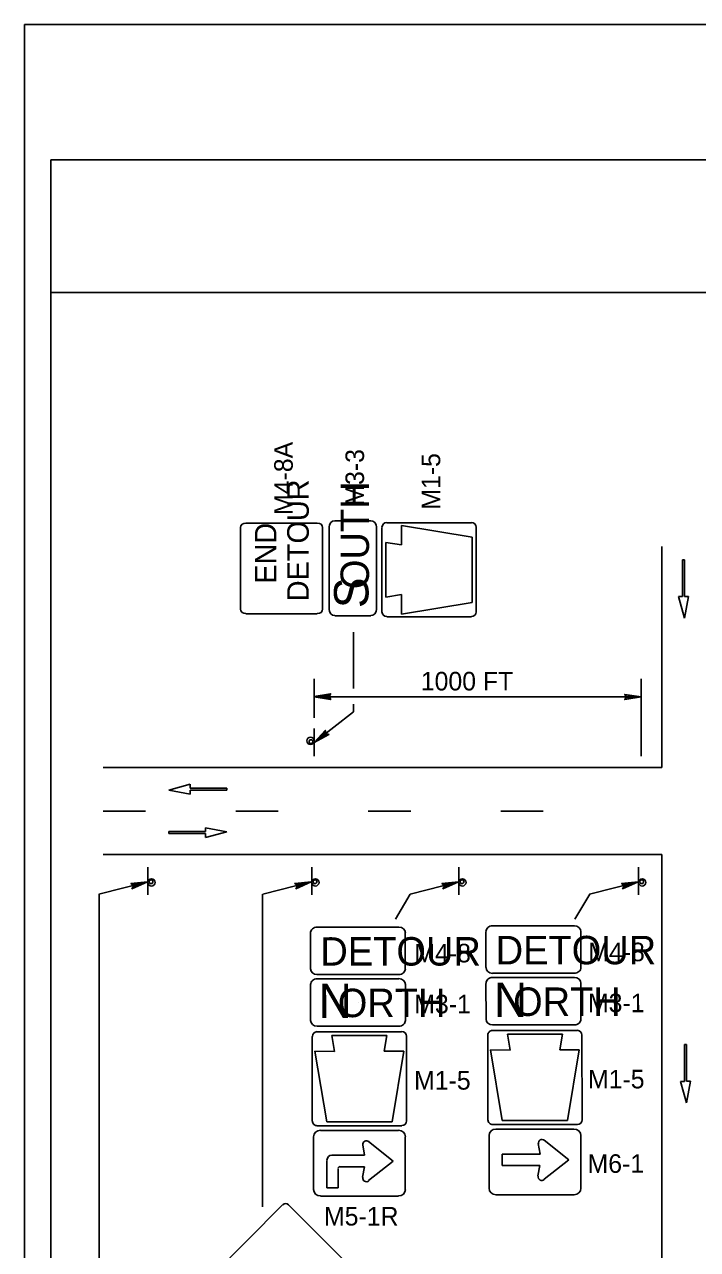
# Model space of a CAD drawing. Extents: x -14145 to -13521, y 30244 to 30661.
# Drawn here: x -13926.17 to -13918.56, y 30274.45 to 30288.31 of the extents above; entities that cross this region are included whole.
import ezdxf

# ---------------------------------------------------------------- set-up
doc = ezdxf.new("R2010")
doc.units = 0
for name, color, linetype in [('1', 7, 'Continuous'), ('10', 7, 'Continuous'), ('2', 7, 'Continuous'), ('61', 7, 'Continuous')]:
    doc.layers.add(name, color=color, linetype=linetype)

msp = doc.modelspace()

# ---------------------------------------------------------------- linework, layer by layer
at = {"layer": '1'}
for p, q in [((-13923.73, 30281.692), (-13923.73, 30282.619)), ((-13923.67, 30282.668), (-13922.863, 30282.668)), ((-13922.803, 30282.619), (-13922.803, 30281.692)), ((-13922.729, 30282.619), (-13922.729, 30281.692)), ((-13922.257, 30282.692), (-13922.663, 30282.692)), ((-13922.192, 30281.692), (-13922.192, 30282.619)), ((-13922.13, 30282.619), (-13922.13, 30281.661)), ((-13921.119, 30282.672), (-13922.077, 30282.672)), ((-13921.111, 30282.509), (-13921.909, 30282.642)), ((-13921.909, 30282.642), (-13921.909, 30282.421)), ((-13921.066, 30281.661), (-13921.066, 30282.619)), ((-13921.909, 30282.421), (-13922.087, 30282.45)), ((-13922.087, 30282.45), (-13922.087, 30282.14)), ((-13921.111, 30282.132), (-13921.111, 30282.509)), ((-13918.966, 30279.902), (-13918.966, 30282.402)), ((-13918.708, 30282.252), (-13918.73, 30282.252)), ((-13918.73, 30282.252), (-13918.73, 30281.836)), ((-13918.708, 30281.838), (-13918.708, 30282.252)), ((-13922.087, 30282.14), (-13922.087, 30281.829)), ((-13921.111, 30281.771), (-13921.111, 30282.148)), ((-13922.087, 30281.829), (-13921.909, 30281.859)), ((-13921.909, 30281.859), (-13921.909, 30281.637)), ((-13921.909, 30281.637), (-13921.111, 30281.771)), ((-13918.73, 30281.836), (-13918.776, 30281.836)), ((-13918.776, 30281.836), (-13918.709, 30281.594)), ((-13918.709, 30281.594), (-13918.663, 30281.838)), ((-13918.663, 30281.838), (-13918.708, 30281.838)), ((-13922.863, 30281.643), (-13923.67, 30281.643)), ((-13922.663, 30281.619), (-13922.257, 30281.619)), ((-13922.077, 30281.607), (-13921.119, 30281.607)), ((-13922.453, 30280.798), (-13922.453, 30281.436)), ((-13922.898, 30280.905), (-13922.898, 30280.465)), ((-13919.198, 30280.905), (-13919.198, 30280.031)), ((-13919.198, 30280.701), (-13922.898, 30280.701)), ((-13919.198, 30280.701), (-13921.048, 30280.701)), ((-13919.198, 30280.701), (-13921.048, 30280.701)), ((-13922.454, 30280.535), (-13922.899, 30280.187)), ((-13922.453, 30280.535), (-13922.453, 30280.619)), ((-13922.899, 30280.031), (-13922.899, 30280.343)), ((-13922.899, 30280.031), (-13922.899, 30280.343)), ((-13922.899, 30280.031), (-13922.899, 30280.343)), ((-13922.899, 30280.031), (-13922.899, 30280.343)), ((-13922.899, 30280.031), (-13922.899, 30280.343)), ((-13922.899, 30280.031), (-13922.899, 30280.343)), ((-13925.284, 30279.902), (-13918.966, 30279.902)), ((-13924.301, 30279.714), (-13924.542, 30279.647)), ((-13924.301, 30279.668), (-13924.301, 30279.714)), ((-13923.884, 30279.668), (-13924.301, 30279.668)), ((-13923.884, 30279.646), (-13923.884, 30279.668)), ((-13924.542, 30279.647), (-13924.298, 30279.601)), ((-13924.298, 30279.601), (-13924.298, 30279.646)), ((-13924.298, 30279.646), (-13923.884, 30279.646)), ((-13924.805, 30279.411), (-13925.285, 30279.411)), ((-13923.305, 30279.411), (-13923.785, 30279.411)), ((-13921.805, 30279.411), (-13922.285, 30279.411)), ((-13920.305, 30279.411), (-13920.785, 30279.411)), ((-13924.128, 30279.178), (-13924.542, 30279.178)), ((-13924.542, 30279.178), (-13924.542, 30279.156)), ((-13924.542, 30279.156), (-13924.126, 30279.156)), ((-13923.884, 30279.177), (-13924.128, 30279.223)), ((-13924.128, 30279.223), (-13924.128, 30279.178)), ((-13924.126, 30279.111), (-13923.884, 30279.177)), ((-13924.126, 30279.156), (-13924.126, 30279.111)), ((-13925.284, 30278.918), (-13918.966, 30278.918)), ((-13918.966, 30270.956), (-13918.966, 30278.918)), ((-13924.778, 30278.777), (-13924.778, 30278.465)), ((-13924.778, 30278.777), (-13924.778, 30278.465)), ((-13924.778, 30278.777), (-13924.778, 30278.465)), ((-13924.778, 30278.777), (-13924.778, 30278.465)), ((-13924.778, 30278.777), (-13924.778, 30278.465)), ((-13924.778, 30278.777), (-13924.778, 30278.465)), ((-13922.924, 30278.777), (-13922.924, 30278.465)), ((-13922.924, 30278.777), (-13922.924, 30278.465)), ((-13922.924, 30278.777), (-13922.924, 30278.465)), ((-13922.924, 30278.777), (-13922.924, 30278.465)), ((-13922.924, 30278.777), (-13922.924, 30278.465)), ((-13922.924, 30278.777), (-13922.924, 30278.465)), ((-13921.26, 30278.777), (-13921.26, 30278.465)), ((-13921.26, 30278.777), (-13921.26, 30278.465)), ((-13921.26, 30278.777), (-13921.26, 30278.465)), ((-13921.26, 30278.777), (-13921.26, 30278.465)), ((-13921.26, 30278.777), (-13921.26, 30278.465)), ((-13921.26, 30278.777), (-13921.26, 30278.465)), ((-13919.228, 30278.777), (-13919.228, 30278.465)), ((-13919.228, 30278.777), (-13919.228, 30278.465)), ((-13919.228, 30278.777), (-13919.228, 30278.465)), ((-13919.228, 30278.777), (-13919.228, 30278.465)), ((-13919.228, 30278.777), (-13919.228, 30278.465)), ((-13919.228, 30278.777), (-13919.228, 30278.465)), ((-13925.331, 30278.47), (-13924.784, 30278.61)), ((-13925.331, 30278.47), (-13924.784, 30278.61)), ((-13923.477, 30278.47), (-13922.93, 30278.61)), ((-13923.477, 30278.47), (-13922.93, 30278.61)), ((-13921.813, 30278.47), (-13921.266, 30278.61)), ((-13921.813, 30278.47), (-13921.266, 30278.61)), ((-13919.781, 30278.47), (-13919.234, 30278.61)), ((-13919.781, 30278.47), (-13919.234, 30278.61)), ((-13925.33, 30278.47), (-13925.33, 30273.816)), ((-13923.48, 30278.47), (-13923.48, 30274.934)), ((-13921.812, 30278.47), (-13921.979, 30278.188)), ((-13919.78, 30278.47), (-13919.947, 30278.188)), ((-13922.94, 30277.627), (-13922.94, 30278.032)), ((-13922.866, 30278.098), (-13921.94, 30278.098)), ((-13921.866, 30278.032), (-13921.866, 30277.627)), ((-13920.955, 30277.641), (-13920.955, 30278.046)), ((-13920.881, 30278.113), (-13919.955, 30278.113)), ((-13919.881, 30278.047), (-13919.881, 30277.642)), ((-13922.938, 30277.042), (-13922.939, 30277.448)), ((-13921.94, 30277.561), (-13922.866, 30277.561)), ((-13922.865, 30277.514), (-13921.938, 30277.514)), ((-13921.865, 30277.448), (-13921.865, 30277.042)), ((-13920.953, 30277.056), (-13920.954, 30277.462)), ((-13919.955, 30277.576), (-13920.881, 30277.576)), ((-13920.881, 30277.529), (-13919.954, 30277.529)), ((-13919.881, 30277.463), (-13919.88, 30277.057)), ((-13922.401, 30277.245), (-13922.401, 30277.245)), ((-13920.416, 30277.259), (-13920.416, 30277.259)), ((-13922.866, 30276.915), (-13921.908, 30276.915)), ((-13921.938, 30276.977), (-13922.865, 30276.977)), ((-13919.953, 30276.992), (-13920.88, 30276.992)), ((-13920.88, 30276.93), (-13919.922, 30276.93)), ((-13920.682, 30276.708), (-13920.711, 30276.887)), ((-13920.711, 30276.887), (-13920.401, 30276.887)), ((-13920.401, 30276.887), (-13920.09, 30276.887)), ((-13920.09, 30276.887), (-13920.12, 30276.709)), ((-13922.918, 30275.904), (-13922.918, 30276.862)), ((-13922.667, 30276.693), (-13922.696, 30276.872)), ((-13922.696, 30276.872), (-13922.386, 30276.872)), ((-13922.386, 30276.872), (-13922.075, 30276.872)), ((-13922.075, 30276.872), (-13922.105, 30276.694)), ((-13921.853, 30276.862), (-13921.852, 30275.904)), ((-13920.932, 30275.918), (-13920.934, 30276.876)), ((-13919.868, 30276.877), (-13919.867, 30275.919)), ((-13918.685, 30276.769), (-13918.707, 30276.769)), ((-13918.707, 30276.769), (-13918.707, 30276.353)), ((-13918.685, 30276.355), (-13918.685, 30276.769)), ((-13922.754, 30275.896), (-13922.888, 30276.694)), ((-13922.888, 30276.694), (-13922.667, 30276.693)), ((-13922.105, 30276.694), (-13921.883, 30276.695)), ((-13921.883, 30276.695), (-13922.016, 30275.896)), ((-13920.769, 30275.91), (-13920.903, 30276.709)), ((-13920.903, 30276.709), (-13920.682, 30276.708)), ((-13920.12, 30276.709), (-13919.898, 30276.709)), ((-13919.898, 30276.709), (-13920.031, 30275.911)), ((-13918.707, 30276.353), (-13918.753, 30276.353)), ((-13918.753, 30276.353), (-13918.686, 30276.111)), ((-13918.686, 30276.111), (-13918.64, 30276.355)), ((-13918.64, 30276.355), (-13918.685, 30276.355)), ((-13921.907, 30275.851), (-13922.865, 30275.851)), ((-13922.826, 30275.798), (-13921.944, 30275.799)), ((-13922.377, 30275.896), (-13922.754, 30275.896)), ((-13922.016, 30275.896), (-13922.393, 30275.896)), ((-13919.922, 30275.866), (-13920.88, 30275.865)), ((-13920.842, 30275.813), (-13919.96, 30275.814)), ((-13920.392, 30275.911), (-13920.769, 30275.91)), ((-13920.031, 30275.911), (-13920.408, 30275.911)), ((-13922.905, 30275.13), (-13922.904, 30275.724)), ((-13922.003, 30275.453), (-13922.281, 30275.672)), ((-13921.866, 30275.726), (-13921.866, 30275.132)), ((-13920.919, 30275.146), (-13920.919, 30275.74)), ((-13920.363, 30275.65), (-13920.342, 30275.532)), ((-13920.017, 30275.468), (-13920.296, 30275.687)), ((-13919.881, 30275.74), (-13919.881, 30275.146)), ((-13922.327, 30275.518), (-13922.699, 30275.518)), ((-13922.348, 30275.636), (-13922.327, 30275.518)), ((-13920.342, 30275.532), (-13920.77, 30275.532)), ((-13920.77, 30275.532), (-13920.769, 30275.403)), ((-13922.755, 30275.458), (-13922.754, 30275.15)), ((-13922.626, 30275.15), (-13922.627, 30275.361)), ((-13922.605, 30275.389), (-13922.329, 30275.389)), ((-13922.329, 30275.389), (-13922.35, 30275.272)), ((-13922.282, 30275.232), (-13922.003, 30275.453)), ((-13920.769, 30275.403), (-13920.343, 30275.403)), ((-13920.343, 30275.403), (-13920.366, 30275.287)), ((-13920.297, 30275.247), (-13920.017, 30275.468)), ((-13922.754, 30275.15), (-13922.626, 30275.15)), ((-13923.254, 30274.958), (-13924.049, 30274.155)), ((-13922.385, 30274.155), (-13923.188, 30274.958)), ((-13921.945, 30275.057), (-13922.827, 30275.056)), ((-13919.959, 30275.071), (-13920.841, 30275.071))]:
    msp.add_line(p, q, dxfattribs=at)
for points in [[(-13922.718, 30280.731), (-13922.724, 30280.719), (-13922.898, 30280.707), (-13922.718, 30280.731), (-13922.712, 30280.737), (-13922.898, 30280.707), (-13922.724, 30280.701), (-13922.718, 30280.689), (-13922.898, 30280.707), (-13922.712, 30280.677), (-13922.718, 30280.689)], [(-13922.718, 30280.731), (-13922.724, 30280.719), (-13922.898, 30280.707), (-13922.718, 30280.731), (-13922.712, 30280.737), (-13922.898, 30280.707), (-13922.724, 30280.701), (-13922.718, 30280.689), (-13922.898, 30280.707), (-13922.712, 30280.677), (-13922.718, 30280.689)], [(-13922.718, 30280.725), (-13922.724, 30280.713), (-13922.898, 30280.701), (-13922.718, 30280.725), (-13922.712, 30280.731), (-13922.898, 30280.701), (-13922.724, 30280.695), (-13922.718, 30280.683), (-13922.898, 30280.701), (-13922.712, 30280.671), (-13922.718, 30280.683)], [(-13919.378, 30280.677), (-13919.372, 30280.695), (-13919.198, 30280.701), (-13919.378, 30280.677), (-13919.384, 30280.671), (-13919.198, 30280.701), (-13919.372, 30280.707), (-13919.378, 30280.725), (-13919.198, 30280.701), (-13919.384, 30280.731), (-13919.378, 30280.725)], [(-13919.378, 30280.677), (-13919.372, 30280.695), (-13919.198, 30280.701), (-13919.378, 30280.677), (-13919.384, 30280.671), (-13919.198, 30280.701), (-13919.372, 30280.707), (-13919.378, 30280.725), (-13919.198, 30280.701), (-13919.384, 30280.731), (-13919.378, 30280.725)], [(-13919.378, 30280.677), (-13919.372, 30280.695), (-13919.198, 30280.701), (-13919.378, 30280.677), (-13919.384, 30280.671), (-13919.198, 30280.701), (-13919.372, 30280.707), (-13919.378, 30280.725), (-13919.198, 30280.701), (-13919.384, 30280.731), (-13919.378, 30280.725)], [(-13922.77, 30280.315), (-13922.768, 30280.298), (-13922.899, 30280.187), (-13922.77, 30280.315), (-13922.771, 30280.323), (-13922.899, 30280.187), (-13922.757, 30280.282), (-13922.744, 30280.28), (-13922.899, 30280.187), (-13922.731, 30280.277), (-13922.744, 30280.28)], [(-13922.77, 30280.315), (-13922.768, 30280.298), (-13922.899, 30280.187), (-13922.77, 30280.315), (-13922.771, 30280.323), (-13922.899, 30280.187), (-13922.757, 30280.282), (-13922.744, 30280.28), (-13922.899, 30280.187), (-13922.731, 30280.277), (-13922.744, 30280.28)], [(-13922.77, 30280.315), (-13922.768, 30280.298), (-13922.899, 30280.187), (-13922.77, 30280.315), (-13922.771, 30280.323), (-13922.899, 30280.187), (-13922.757, 30280.282), (-13922.744, 30280.28), (-13922.899, 30280.187), (-13922.731, 30280.277), (-13922.744, 30280.28)], [(-13924.964, 30278.586), (-13924.952, 30278.574), (-13924.784, 30278.61), (-13924.964, 30278.586), (-13924.97, 30278.592), (-13924.784, 30278.61), (-13924.946, 30278.556), (-13924.952, 30278.544), (-13924.784, 30278.61), (-13924.958, 30278.532), (-13924.952, 30278.544)], [(-13924.964, 30278.586), (-13924.952, 30278.574), (-13924.784, 30278.61), (-13924.964, 30278.586), (-13924.97, 30278.592), (-13924.784, 30278.61), (-13924.946, 30278.556), (-13924.952, 30278.544), (-13924.784, 30278.61), (-13924.958, 30278.532), (-13924.952, 30278.544)], [(-13924.964, 30278.586), (-13924.952, 30278.574), (-13924.784, 30278.61), (-13924.964, 30278.586), (-13924.97, 30278.592), (-13924.784, 30278.61), (-13924.946, 30278.556), (-13924.952, 30278.544), (-13924.784, 30278.61), (-13924.958, 30278.532), (-13924.952, 30278.544)], [(-13923.11, 30278.586), (-13923.098, 30278.574), (-13922.93, 30278.61), (-13923.11, 30278.586), (-13923.116, 30278.592), (-13922.93, 30278.61), (-13923.092, 30278.556), (-13923.098, 30278.544), (-13922.93, 30278.61), (-13923.104, 30278.532), (-13923.098, 30278.544)], [(-13923.11, 30278.586), (-13923.098, 30278.574), (-13922.93, 30278.61), (-13923.11, 30278.586), (-13923.116, 30278.592), (-13922.93, 30278.61), (-13923.092, 30278.556), (-13923.098, 30278.544), (-13922.93, 30278.61), (-13923.104, 30278.532), (-13923.098, 30278.544)], [(-13923.11, 30278.586), (-13923.098, 30278.574), (-13922.93, 30278.61), (-13923.11, 30278.586), (-13923.116, 30278.592), (-13922.93, 30278.61), (-13923.092, 30278.556), (-13923.098, 30278.544), (-13922.93, 30278.61), (-13923.104, 30278.532), (-13923.098, 30278.544)], [(-13921.446, 30278.586), (-13921.434, 30278.574), (-13921.266, 30278.61), (-13921.446, 30278.586), (-13921.452, 30278.592), (-13921.266, 30278.61), (-13921.428, 30278.556), (-13921.434, 30278.544), (-13921.266, 30278.61), (-13921.44, 30278.532), (-13921.434, 30278.544)], [(-13921.446, 30278.586), (-13921.434, 30278.574), (-13921.266, 30278.61), (-13921.446, 30278.586), (-13921.452, 30278.592), (-13921.266, 30278.61), (-13921.428, 30278.556), (-13921.434, 30278.544), (-13921.266, 30278.61), (-13921.44, 30278.532), (-13921.434, 30278.544)], [(-13921.446, 30278.586), (-13921.434, 30278.574), (-13921.266, 30278.61), (-13921.446, 30278.586), (-13921.452, 30278.592), (-13921.266, 30278.61), (-13921.428, 30278.556), (-13921.434, 30278.544), (-13921.266, 30278.61), (-13921.44, 30278.532), (-13921.434, 30278.544)], [(-13919.414, 30278.586), (-13919.402, 30278.574), (-13919.234, 30278.61), (-13919.414, 30278.586), (-13919.42, 30278.592), (-13919.234, 30278.61), (-13919.396, 30278.556), (-13919.402, 30278.544), (-13919.234, 30278.61), (-13919.408, 30278.532), (-13919.402, 30278.544)], [(-13919.414, 30278.586), (-13919.402, 30278.574), (-13919.234, 30278.61), (-13919.414, 30278.586), (-13919.42, 30278.592), (-13919.234, 30278.61), (-13919.396, 30278.556), (-13919.402, 30278.544), (-13919.234, 30278.61), (-13919.408, 30278.532), (-13919.402, 30278.544)], [(-13919.414, 30278.586), (-13919.402, 30278.574), (-13919.234, 30278.61), (-13919.414, 30278.586), (-13919.42, 30278.592), (-13919.234, 30278.61), (-13919.396, 30278.556), (-13919.402, 30278.544), (-13919.234, 30278.61), (-13919.408, 30278.532), (-13919.402, 30278.544)]]:
    msp.add_lwpolyline(points, dxfattribs=at)
for centre in [(-13922.939, 30280.205), (-13922.939, 30280.205), (-13922.939, 30280.205), (-13924.737, 30278.604), (-13924.737, 30278.604), (-13924.737, 30278.604), (-13922.883, 30278.604), (-13922.883, 30278.604), (-13922.883, 30278.604), (-13921.22, 30278.604), (-13921.22, 30278.604), (-13921.22, 30278.604), (-13919.186, 30278.604), (-13919.186, 30278.604), (-13919.186, 30278.604)]:
    msp.add_circle(centre, 0.0408, dxfattribs=at)
for centre, radius, start, end in [((-13922.077, 30282.621), 0.0532, 90, 180), ((-13921.119, 30282.621), 0.0532, 0, 90), ((-13922.077, 30281.663), 0.0532, 180, 270), ((-13921.119, 30281.663), 0.0532, 270, 0), ((-13922.934, 30280.197), 0.0214, 9.521, 4.2501), ((-13922.934, 30280.197), 0.0214, 9.521, 4.2501), ((-13922.934, 30280.197), 0.0214, 9.521, 4.2501), ((-13924.742, 30278.611), 0.0214, 189.521, 184.2501), ((-13924.742, 30278.611), 0.0214, 189.521, 184.2501), ((-13924.742, 30278.611), 0.0214, 189.521, 184.2501), ((-13922.888, 30278.611), 0.0214, 189.521, 184.2501), ((-13922.888, 30278.611), 0.0214, 189.521, 184.2501), ((-13922.888, 30278.611), 0.0214, 189.521, 184.2501), ((-13921.225, 30278.611), 0.0214, 189.521, 184.2501), ((-13921.225, 30278.611), 0.0214, 189.521, 184.2501), ((-13921.225, 30278.611), 0.0214, 189.521, 184.2501), ((-13919.192, 30278.611), 0.0214, 189.521, 184.2501), ((-13919.192, 30278.611), 0.0214, 189.521, 184.2501), ((-13919.192, 30278.611), 0.0214, 189.521, 184.2501), ((-13922.864, 30276.863), 0.0532, 90.0305, 180.0305), ((-13921.906, 30276.864), 0.0532, 0.0305, 90.0305), ((-13920.879, 30276.877), 0.0532, 90.0332, 180.0332), ((-13919.921, 30276.878), 0.0532, 0.0332, 90.0332), ((-13920.878, 30275.919), 0.0532, 180.0332, 270.0332), ((-13919.92, 30275.919), 0.0532, 270.0332, 0.0332), ((-13922.863, 30275.905), 0.0532, 180.0305, 270.0305), ((-13921.905, 30275.906), 0.0532, 270.0305, 0.0305), ((-13922.305, 30275.641), 0.0414, 49.8897, 190.5552), ((-13920.32, 30275.655), 0.0414, 49.8923, 190.5579), ((-13922.697, 30275.464), 0.0554, 90.0305, 180.0305), ((-13922.604, 30275.368), 0.0222, 90.0305, 180.0305), ((-13922.307, 30275.26), 0.0414, 168.2781, 312.1848), ((-13920.322, 30275.274), 0.0414, 168.2808, 312.1874), ((-13923.22, 30274.925), 0.0465, 45, 135)]:
    msp.add_arc(centre, radius, start, end, dxfattribs=at)
for centre, major_axis, ratio, start_param, end_param in [((-13923.67, 30282.619), (-0.0602, 0), 0.817773, 4.712389, 6.283185), ((-13922.862, 30282.619), (-0.0602, 0), 0.817773, 3.141593, 4.712389), ((-13922.663, 30282.621), (0, 0.0734), 0.893242, 0, 1.570796), ((-13922.258, 30282.621), (0, 0.0734), 0.893242, 4.712389, 6.283185), ((-13923.67, 30281.693), (0.0602, 0), 0.817773, 3.141593, 4.712389), ((-13922.862, 30281.693), (0.0602, 0), 0.817773, 4.712389, 6.283185), ((-13922.663, 30281.695), (0, -0.0734), 0.893242, 4.712389, 6.283185), ((-13922.258, 30281.695), (0, -0.0734), 0.893242, 0, 1.570796), ((-13922.865, 30278.033), (0.0734, 0), 0.893242, 1.570796, 3.141593), ((-13921.939, 30278.033), (-0.0734, 0), 0.893242, 3.141593, 4.712389), ((-13920.881, 30278.047), (0.0734, 0), 0.893242, 1.570796, 3.141593), ((-13919.954, 30278.047), (-0.0734, 0), 0.893242, 3.141593, 4.712389), ((-13922.865, 30277.627), (0.0734, 0), 0.893242, 3.141593, 4.712389), ((-13921.939, 30277.628), (-0.0734, 0), 0.893242, 1.570796, 3.141593), ((-13920.88, 30277.641), (0.0734, 0), 0.893242, 3.141593, 4.712389), ((-13919.954, 30277.642), (-0.0734, 0), 0.893242, 1.570796, 3.141593), ((-13922.864, 30277.449), (0.0734, 0), 0.893242, 1.570796, 3.141593), ((-13921.938, 30277.45), (-0.0734, 0), 0.893242, 3.141593, 4.712389), ((-13920.88, 30277.463), (0.0734, 0), 0.893242, 1.570796, 3.141593), ((-13919.953, 30277.463), (-0.0734, 0), 0.893242, 3.141593, 4.712389), ((-13922.864, 30277.044), (0.0734, 0), 0.893242, 3.141593, 4.712389), ((-13921.938, 30277.044), (-0.0734, 0), 0.893242, 1.570796, 3.141593), ((-13920.879, 30277.057), (0.0734, 0), 0.893242, 3.141593, 4.712389), ((-13919.953, 30277.058), (-0.0734, 0), 0.893242, 1.570796, 3.141593), ((-13922.825, 30275.726), (-0.0789, 0), 0.941916, 4.712389, 6.283185), ((-13921.943, 30275.726), (0.0789, 0), 0.941916, 0, 1.570796), ((-13920.84, 30275.74), (-0.0789, 0), 0.941916, 4.712389, 6.283185), ((-13919.959, 30275.74), (0.0789, 0), 0.941916, 0, 1.570796), ((-13922.825, 30275.132), (-0.0789, 0), 0.941916, 0, 1.570796), ((-13921.943, 30275.132), (0.0789, 0), 0.941916, 4.712389, 6.283185), ((-13920.84, 30275.146), (-0.0789, 0), 0.941916, 0, 1.570796), ((-13919.958, 30275.146), (0.0789, 0), 0.941916, 4.712389, 6.283185)]:
    msp.add_ellipse(centre, major_axis=major_axis, ratio=ratio, start_param=start_param, end_param=end_param, dxfattribs=at)
at = {"layer": '10'}
for p, q in [((-13925.874, 30286.777), (-13894.422, 30286.777)), ((-13925.874, 30264.207), (-13925.874, 30286.777)), ((-13925.874, 30285.277), (-13894.422, 30285.277))]:
    msp.add_line(p, q, dxfattribs=at)
at = {"layer": '61'}
msp.add_lwpolyline([(-13926.174, 30288.307), (-13893.174, 30288.307), (-13893.174, 30262.807), (-13926.174, 30262.807)], close=True, dxfattribs=at)

# ---------------------------------------------------------------- texts
at = {"layer": '1'}
for s, height, rotation, p in [('DETOUR', 0.244, 90, (-13922.958, 30281.784)), ('OUTH', 0.3216, 90, (-13922.277, 30281.921)), ('END', 0.244, 90, (-13923.324, 30281.982)), ('S', 0.389, 90, (-13922.283, 30281.706)), ('DETOUR', 0.3216, 0.0332, (-13920.844, 30277.677)), ('DETOUR', 0.3216, 0.0305, (-13922.827, 30277.663)), ('N', 0.389, 0.0305, (-13922.847, 30277.069)), ('N', 0.389, 0.0332, (-13920.863, 30277.082)), ('ORTH', 0.3216, 0.0305, (-13922.63, 30277.08)), ('ORTH', 0.3216, 0.0332, (-13920.647, 30277.094))]:
    msp.add_text(s, height=height, rotation=rotation, dxfattribs=at).set_placement(p)
at = {"layer": '2'}
for s, rotation, p in [('M4-8A', 90, (-13923.139, 30282.76)), ('M3-3', 90, (-13922.333, 30282.865)), ('M1-5', 90, (-13921.471, 30282.819)), ('M4-8', 0.0305, (-13921.764, 30277.699)), ('M4-8', 0.0332, (-13919.797, 30277.712)), ('M3-1', 0.0305, (-13921.765, 30277.123)), ('M3-1', 0.0332, (-13919.8, 30277.136)), ('M1-5', 0.0305, (-13921.767, 30276.26)), ('M1-5', 0.0332, (-13919.8, 30276.274)), ('M6-1', 0.0332, (-13919.805, 30275.319)), ('M5-1R', 0.0305, (-13922.786, 30274.723))]:
    msp.add_text(s, height=0.21, rotation=rotation, dxfattribs=at).set_placement(p)
msp.add_text('1000 FT', height=0.21, dxfattribs=at).set_placement((-13921.691, 30280.775))

doc.saveas('drawing.dxf')
